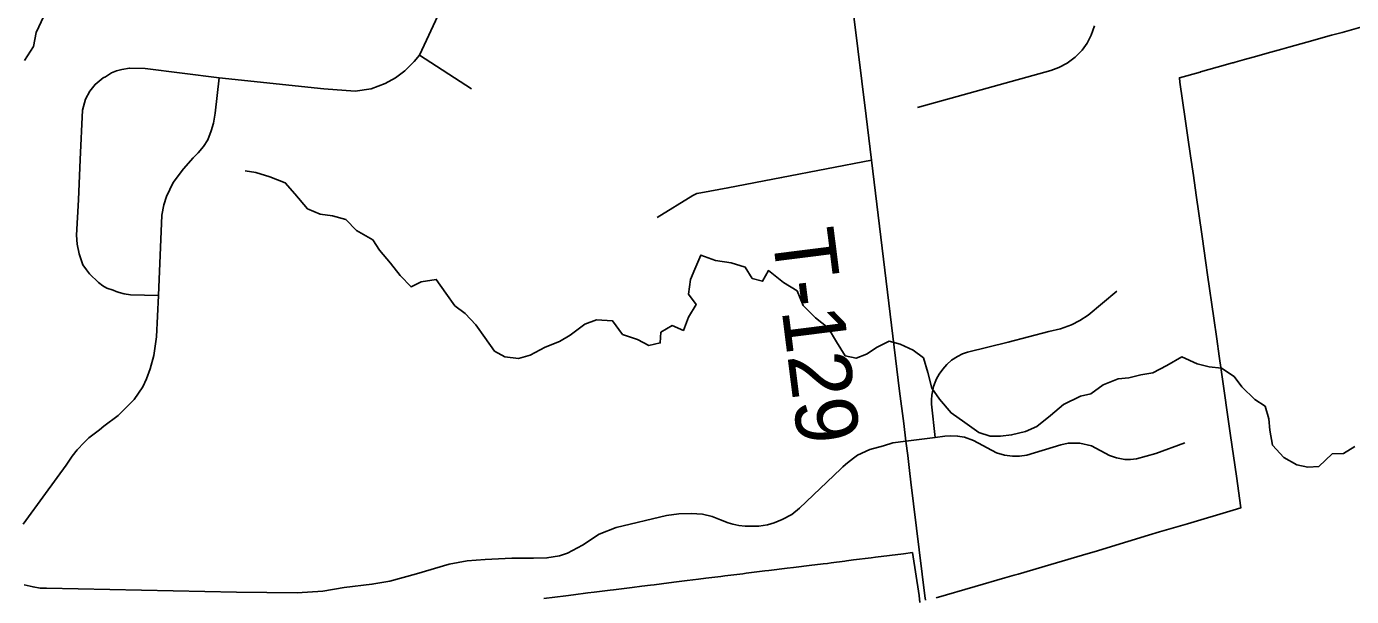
# Model space of a CAD drawing. Extents: x 114843 to 284848, y 317643 to 566895.
# Drawn here: x 158973 to 165392, y 456053 to 458815 of the extents above; entities that cross this region are included whole.
import ezdxf

# ---------------------------------------------------------------- set-up
doc = ezdxf.new("R2010")
doc.units = 0
for name, color, linetype in [('GM_X_Corporation', 7, 'Continuous'), ('GM_X_Minor_River', 7, 'Continuous'), ('GM_X_Township_Road', 7, 'Continuous'), ('GM_X_Township_Road_Text', 7, 'Continuous')]:
    doc.layers.add(name, color=color, linetype=linetype)

msp = doc.modelspace()

# ---------------------------------------------------------------- linework, layer by layer
at = {"layer": 'GM_X_Corporation'}
for points in [[(163379.8, 456045.7), (163569.7, 456100.8), (163713.5, 456142.7), (163758.1, 456155.4), (163777.5, 456160.9), (163935.3, 456207.5), (164116.2, 456261), (164145, 456269.5), (164309.5, 456319.4), (164408.1, 456349.3), (164462.3, 456365.4), (164597.8, 456405.7), (164819, 456471.4), (164856.1, 456482.4), (164835.1, 456636.4), (164806.9, 456832.7), (164761.3, 457151.2), (164751.9, 457217.1), (164739.9, 457300.9), (164725.4, 457401.5), (164695.3, 457611.6), (164686.9, 457670.3), (164668.7, 457797), (164652.8, 457907.9), (164640, 457997.2), (164626.3, 458092.9), (164612.6, 458188.3), (164599.8, 458277.4), (164587, 458366.6), (164561.5, 458544.8), (164558.4, 458566.4), (164658.8, 458594.2), (164661.5, 458594.9), (164742.3, 458617.6), (164815.7, 458638.1), (164819.3, 458639.2), (164829, 458641.9), (164873.6, 458654.3), (164915.7, 458666), (165002.4, 458690.2), (165054.7, 458704.8), (165089.1, 458714.4), (165175.8, 458738.6), (165295.5, 458772), (165346.7, 458786.2), (165448.3, 458814.3)], [(161478.6, 456043.2), (161585.8, 456056.6), (161623.7, 456061.3), (161693, 456069.9), (161722.9, 456073.6), (161800.2, 456083.2), (161817.2, 456085.3), (161907.4, 456096.6), (161953.3, 456102.3), (161995.9, 456107.6), (162014.5, 456109.9), (162085.2, 456118.7), (162121.7, 456123.2), (162174.3, 456129.8), (162228.8, 456136.6), (162263.7, 456140.9), (162336, 456149.9), (162356.8, 456152.5), (162443.2, 456163.2), (162458.8, 456165.2), (162550.4, 456176.6), (162569.2, 456178.9), (162657.5, 456189.9), (162688.2, 456193.7), (162728.3, 456198.7), (162739, 456200.4), (162764.7, 456203.4), (162832.8, 456211.4), (162853.1, 456212.9), (162872, 456215.5), (162937, 456224.7), (162946.4, 456225.8), (162979, 456229.9), (163065.3, 456240.6), (163086.2, 456243.2), (163222.5, 456260.2), (163264.8, 456265.4), (163297.5, 456057.1), (163301.4, 456024.4)]]:
    msp.add_lwpolyline(points, dxfattribs=at)
at = {"layer": 'GM_X_Minor_River'}
for points in [[(159055.8, 458864.2), (159020.1, 458785.8), (159006.3, 458717.6), (158962.5, 458649.3)], [(160334.8, 457931.4), (160272.3, 458003.3), (160226, 458057.3), (160151.7, 458087), (160083.4, 458106.8), (160031.3, 458114.6)], [(165409.4, 456780.3), (165353.5, 456746), (165299.3, 456743.8), (165233.5, 456683.4), (165181.4, 456679.1), (165127.2, 456690.9), (165064.9, 456726.7), (165010.5, 456786.7), (164996.1, 456858.8), (164991.9, 456912.9), (164973.6, 456974.9), (164923.3, 457006.8), (164860.9, 457068.7), (164824.6, 457118.7), (164762.3, 457158.5), (164702.1, 457166.3), (164643.9, 457180), (164569.6, 457213.8), (164497.6, 457171.4), (164429.6, 457137), (164371.5, 457126.7), (164313.5, 457112.5), (164261.3, 457108.2), (164189.3, 457077.8), (164129.4, 457035.5), (164079.3, 457023.3), (163997.3, 456982.8), (163933.4, 456930.4), (163867.5, 456876), (163813.5, 456851.7), (163745.4, 456835.4), (163691.3, 456829.1), (163641.2, 456828.9), (163587, 456846.7), (163518.6, 456896.6), (163452.2, 456942.4), (163395.8, 457008.3), (163359.5, 457062.3), (163339.1, 457138.4), (163318.8, 457208.5), (163268.5, 457246.3), (163206.2, 457276.1), (163152, 457289.9), (163094, 457261.6), (163042.1, 457227.3), (162992, 457207), (162939.8, 457218.8), (162897.4, 457286.8), (162857.1, 457354.8), (162794.7, 457402.7), (162736.3, 457462.6), (162705.9, 457534.6), (162639.6, 457574.4), (162567.2, 457632.3), (162539.3, 457580), (162489.2, 457593.8), (162454.8, 457647.8), (162386.6, 457669.6), (162310.4, 457681.3), (162240.1, 457707), (162210.3, 457638.7), (162190.5, 457588.5), (162180.8, 457518.3), (162217.1, 457468.4), (162179.3, 457406.1), (162155.5, 457341.8), (162101.3, 457365.6), (162045.3, 457333.3), (162043.5, 457281.2), (161987.5, 457268.9), (161933.2, 457298.8), (161860.9, 457322.5), (161812.5, 457388.4), (161734.3, 457394.1), (161678.3, 457371.8), (161606.4, 457319.4), (161554.4, 457289.1), (161486.4, 457260.7), (161412.4, 457222.3), (161356.3, 457206.1), (161290.1, 457213.8), (161239.9, 457241.7), (161193.5, 457307.6), (161149.1, 457369.6), (161098.8, 457423.5), (161048.5, 457461.4), (161004.1, 457523.3), (160957.7, 457589.3), (160885.6, 457576.9), (160835.6, 457552.7), (160783.2, 457608.6), (160736.9, 457668.5), (160682.5, 457730.4), (160650.2, 457780.4), (160571.8, 457826.2), (160519.4, 457880.1), (160455.2, 457897.9), (160395, 457905.6), (160334.8, 457931.4)]]:
    msp.add_lwpolyline(points, dxfattribs=at)
at = {"layer": 'GM_X_Township_Road'}
msp.add_line((160876.4, 458675.5), (161129.3, 458512.4), dxfattribs=at)
for points in [[(163327.9, 456035.6), (163325.4, 456056.5), (163257.6, 456606.1), (163250.5, 456663.5), (163243.2, 456736.2), (163233.1, 456805.1), (163223.7, 456890.7), (163202.8, 457048.1), (163067, 458167.8), (163041.3, 458379.8), (162980.3, 458875.3), (162827.9, 460096.9), (162760.9, 460641.6), (162728.5, 460913.7), (162676.8, 461335.9), (162667.3, 461517.2), (162685.6, 461550.3)], [(159611.4, 457511.8), (159476.2, 457514.5), (159445.9, 457519.1), (159421.1, 457525.5), (159406.5, 457530.5), (159392.1, 457536.4), (159362.1, 457546.3), (159342.1, 457558.1), (159321, 457574), (159278.2, 457615.9), (159262.6, 457635), (159246, 457659.5), (159227.8, 457712.4), (159217.3, 457759.2), (159214.4, 457802.9), (159224.2, 457974.8), (159233.3, 458169.8), (159244.5, 458409.7), (159258.5, 458462.7), (159279.4, 458501.9), (159304.5, 458534), (159344, 458565.9), (159355.8, 458571.4), (159384.7, 458590.4), (159409.4, 458599.6), (159434.6, 458606.5), (159471, 458613.5), (159547.3, 458611.9), (159906.4, 458566.7), (160414, 458512.6), (160565.1, 458501.4), (160642.2, 458513.1), (160710.3, 458538.2), (160761.1, 458566), (160805.2, 458599.6), (160851.5, 458645), (160876.4, 458675.5), (160977, 458890.3)], [(163290, 458421.9), (163935.1, 458601.7), (163974.6, 458615.8), (164014.1, 458636.5), (164054, 458666.1), (164086.9, 458699.9), (164111.4, 458733.8), (164131.9, 458773.2), (164147, 458817.6)], [(158956.6, 456403.8), (159065.2, 456552.4), (159164.5, 456688.7), (159193.6, 456732.1), (159218.3, 456764), (159251.3, 456798.4), (159274.6, 456822.1), (159326.2, 456860.6), (159347.7, 456878.2), (159416.3, 456929.1), (159495, 457007.2), (159536.4, 457069.1), (159554.2, 457107.8), (159571.8, 457156.4), (159589.4, 457220.6), (159601.7, 457311.3), (159611.4, 457511.8), (159628.7, 457901.2), (159637.9, 457951), (159650.7, 457991.3), (159682.5, 458059.6), (159733.5, 458124.6), (159780.8, 458178.6), (159803.8, 458202), (159830, 458234), (159851, 458266.3), (159867.9, 458308.5), (159879.1, 458346), (159886.3, 458394.3), (159906.4, 458566.7)], [(162028.5, 457889.6), (162200.8, 457995.3), (162220.5, 458004.9), (162239.4, 458008.5), (162371.4, 458032.2), (162631.5, 458082.7), (163067, 458167.8)], [(163376, 456822.7), (163357.9, 456984.8), (163357.6, 457006.5), (163359.2, 457028.1), (163361.8, 457045.3), (163367.9, 457070.6), (163375, 457091.1), (163381.9, 457107), (163394.4, 457129.9), (163411.8, 457154.8), (163432.1, 457177.3), (163455, 457197.3), (163483.9, 457216.5), (163507.2, 457228.2), (163531.6, 457237.4), (163729.4, 457284.8), (163926, 457336.5), (163982.5, 457350.4), (164035.3, 457368.7), (164076.7, 457389.7), (164115.8, 457415.8), (164256, 457532.7)], [(163233.1, 456805.1), (163170.4, 456797.2), (163124.8, 456783.6), (163059.1, 456764.7), (162999.5, 456737.9), (162986.1, 456727.7)], [(163233.1, 456805.1), (163376, 456822.7), (163422.4, 456829.1), (163451, 456832), (163483.7, 456830.5), (163516.8, 456824.7), (163561.5, 456808.5), (163673.2, 456748.4), (163710.5, 456737.1), (163749.3, 456732), (163784.2, 456732.7), (163818.9, 456738.3), (163984.8, 456788.3), (164019.1, 456795.2), (164075.6, 456795.9), (164132.1, 456783.1), (164220, 456736.5), (164254.2, 456724.2), (164294.6, 456717.4), (164321.7, 456716.6), (164351.2, 456719.6), (164444.3, 456745.4), (164584.2, 456796.6)], [(162986.1, 456727.7), (162959.3, 456707.4), (162940.4, 456692.5), (162927.8, 456681.3), (162919.9, 456673.8), (162917.4, 456671.3), (162718.5, 456480.2), (162681.3, 456450.9), (162634.7, 456425.2), (162595.5, 456410), (162562.2, 456400.3), (162521.5, 456394), (162477.9, 456393.7), (162454.1, 456394.2), (162424.4, 456397.4), (162395.2, 456403.3), (162372.3, 456410), (162334.5, 456425), (162294.4, 456439.9), (162248.5, 456451.5), (162192.4, 456454.8), (162133.6, 456453.4), (162073.9, 456445.5), (161829.4, 456386.5), (161747.3, 456354.2), (161666.7, 456301.6), (161594.3, 456263.4), (161555.8, 456250.2), (161494.3, 456239.7), (161429.1, 456238.2), (161324.5, 456238), (161195.3, 456232.2), (161107.6, 456225.4), (161020, 456208.9), (160862.3, 456162.5), (160733.8, 456127.2), (160646.3, 456112.1), (160511, 456096.3), (160407.8, 456079.3), (160284, 456070.6), (159989.5, 456073.6), (159069.1, 456093.7), (159039, 456094), (159004.1, 456099.4), (158960.8, 456109.9)]]:
    msp.add_lwpolyline(points, dxfattribs=at)

# ---------------------------------------------------------------- texts
at = {"layer": 'GM_X_Township_Road_Text'}
msp.add_text('T-129', height=300, rotation=277.18811, dxfattribs=at).set_placement((162583.8, 457817.1))

doc.saveas('drawing.dxf')
